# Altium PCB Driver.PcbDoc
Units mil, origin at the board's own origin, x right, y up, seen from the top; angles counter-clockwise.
Board outline 3750 x 2325 mil, 2 copper layers (Top Layer, Bottom Layer); 49 components, 30 nets, 142 pads, 61 vias.
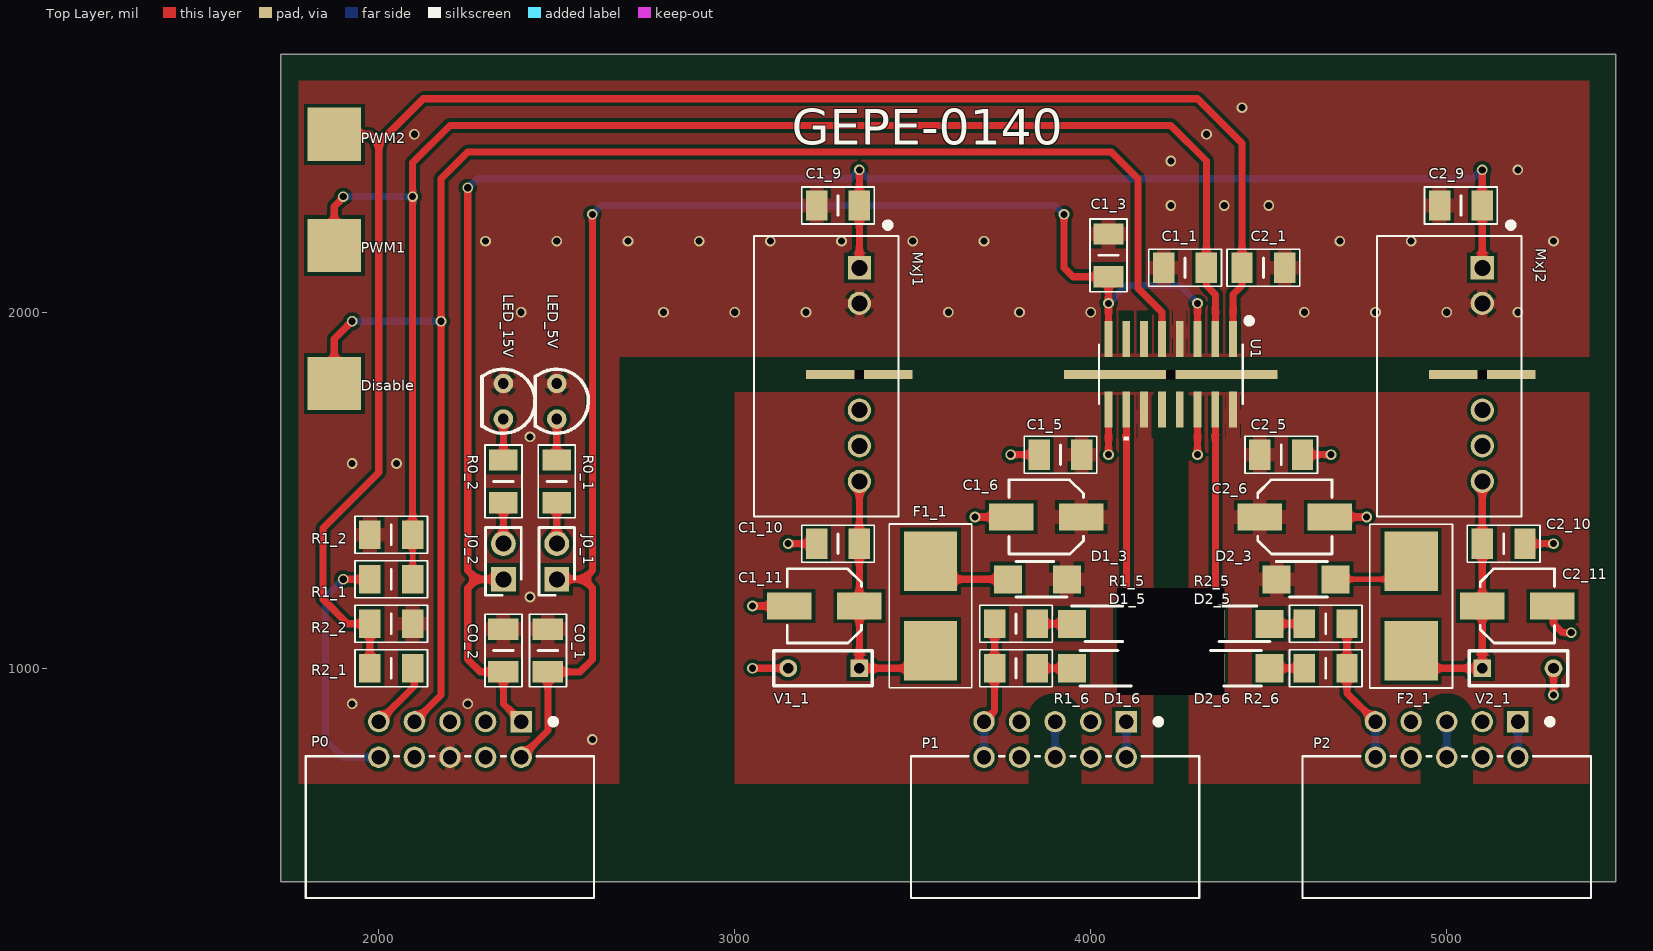
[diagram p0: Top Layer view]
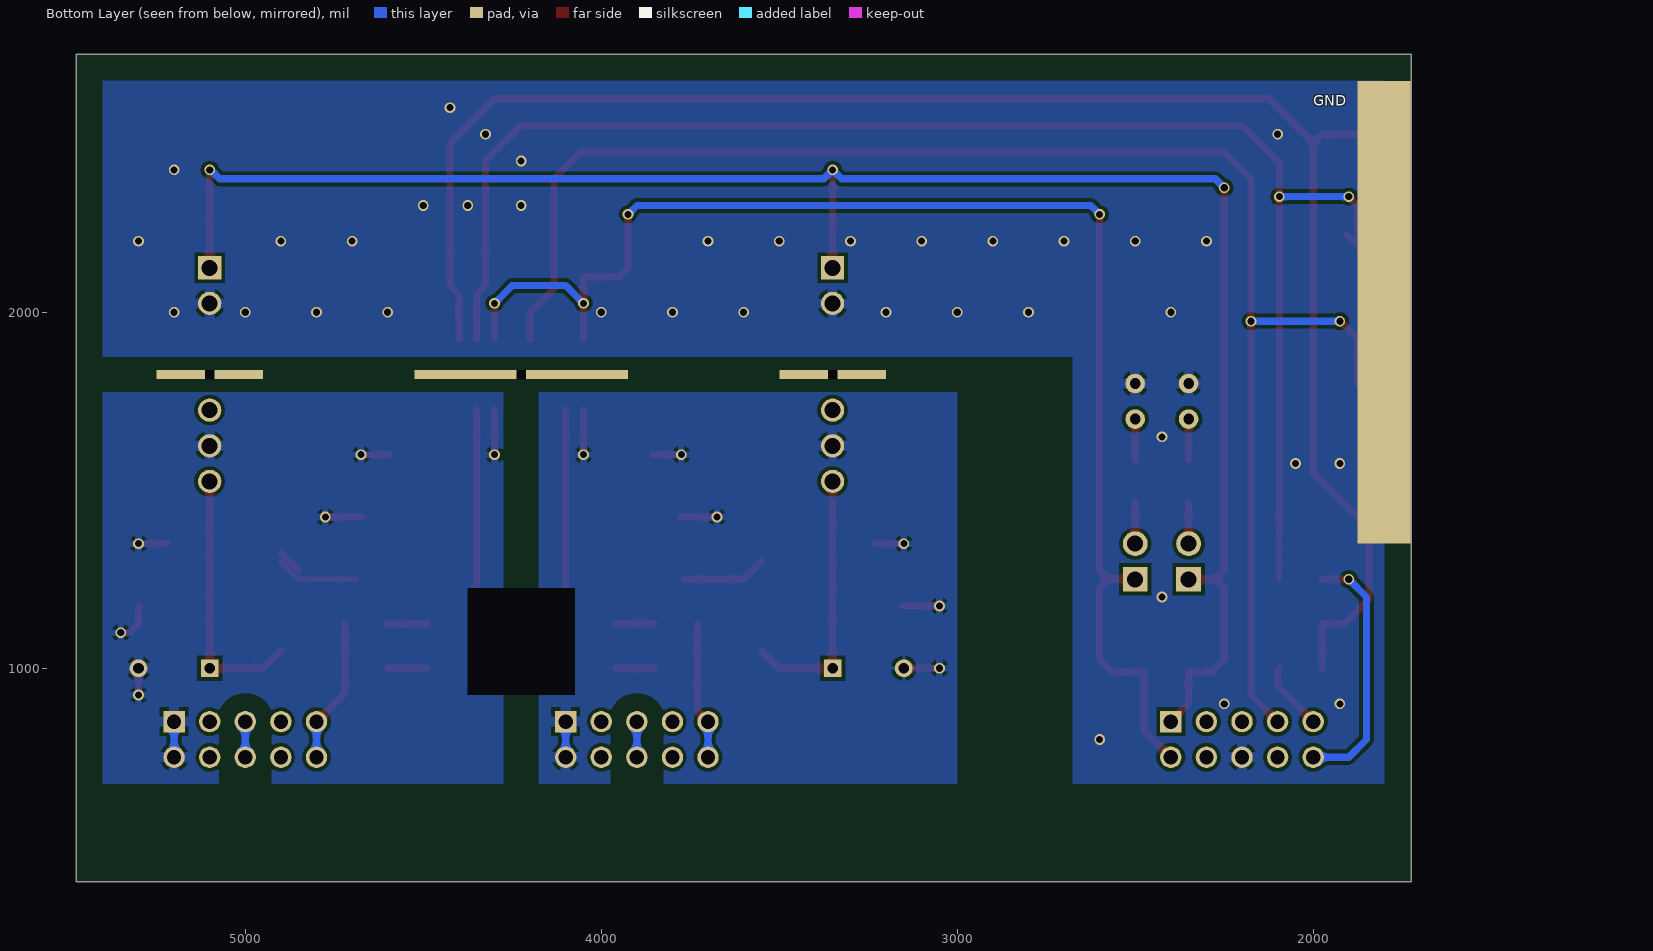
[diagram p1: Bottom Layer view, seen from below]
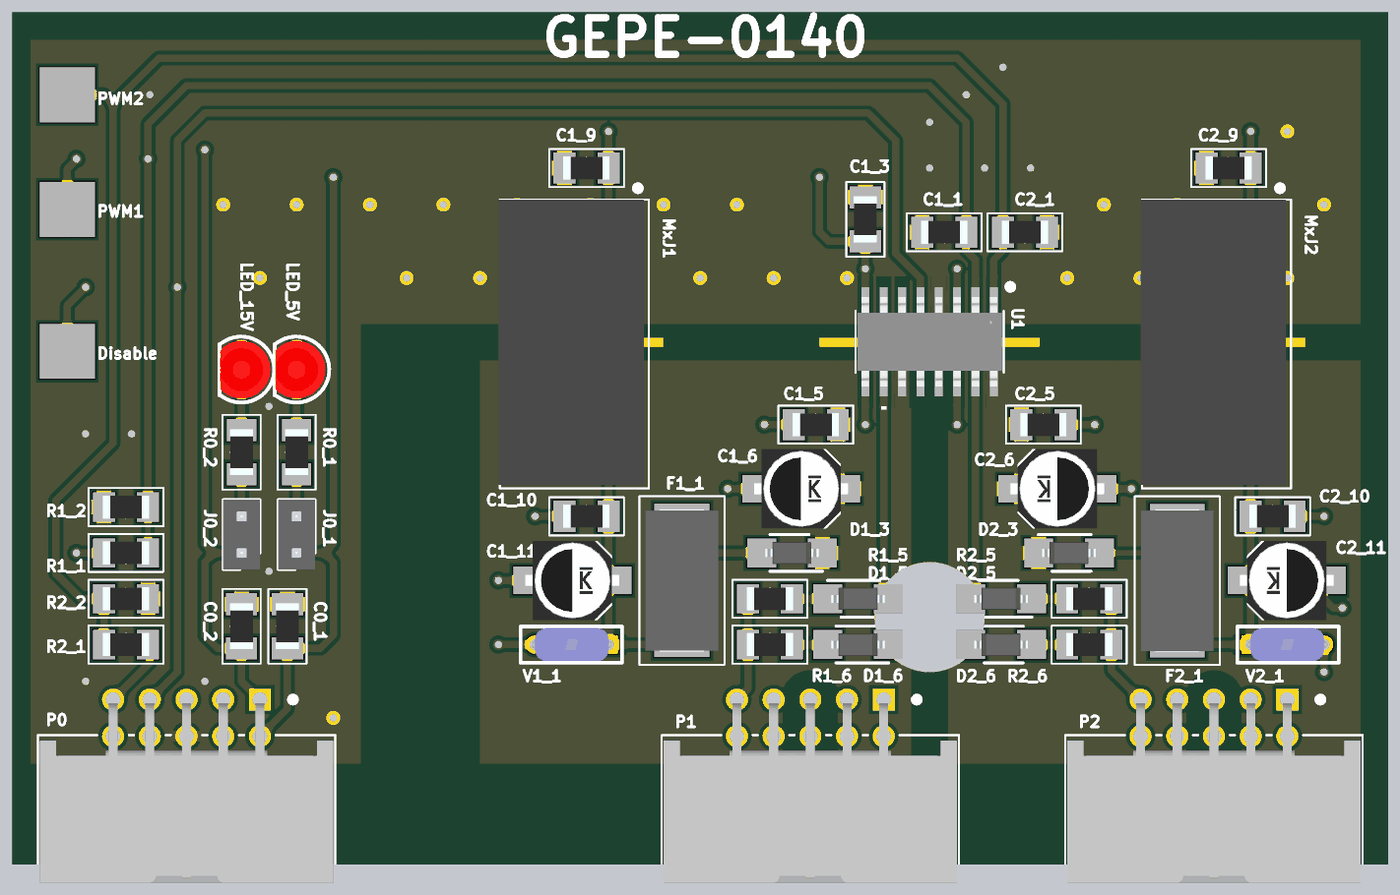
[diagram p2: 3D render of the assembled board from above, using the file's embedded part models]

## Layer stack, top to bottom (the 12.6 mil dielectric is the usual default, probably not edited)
Top Solder: solder mask 0.4, Solder Resist, Dk 3.5
Top Layer: signal copper 1.4
Dielectric 1: dielectric 12.6, FR-4, Dk 4.8
Bottom Layer: signal copper 1.4
Bottom Solder: solder mask 0.4, Solder Resist, Dk 3.5

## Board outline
1725,2725 5475,2725 5475,400 1725,400

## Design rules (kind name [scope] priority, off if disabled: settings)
Clearance Clearance_NetP2_5_GND [InNet('NetP2_5') vs InNet('GND_ISO2')] p1: gap=50 ignorepadtopadclearanceinfootprint=FALSE
Clearance Clearance_NetP2_Vcc [InNet('NetP2_5') vs InNet('NetC2_5_1')] p2: gap=50 ignorepadtopadclearanceinfootprint=FALSE
Clearance Clearance_NetP1_5_GND [InNet('NetP1_5') vs InNet('GND_ISO1')] p3: gap=50 ignorepadtopadclearanceinfootprint=FALSE
Clearance Clearance_NetP1_5_Vcc [InNet('NetP1_5') vs InNet('NetC1_5_1')] p4: gap=50 ignorepadtopadclearanceinfootprint=FALSE
Clearance "Stitching GND_ISO2" [IsStitchingVia and InNet('GND_ISO2') vs (IsVia and (Not IsStitchingVia)) Or IsPad] p5: gap=10 ignorepadtopadclearanceinfootprint=FALSE
Clearance [All] p6: gap=10 ignorepadtopadclearanceinfootprint=FALSE
ComponentClearance [All] p1: gap=-5 collisioncheckmode=3 verticalgap=10 showdistances=FALSE
DiffPairsRouting [All] p1: maxlimit=10 minlimit=10 mostfreqgap=10 substack1={C0840327-101B-4FFC-97E3-E8047B987EDC} toplayer_{c0840327-101b-4ffc-97e3-e8047b987edc}_minwidth=15 toplayer_{c0840327-101b-4ffc-97e3-e8047b987edc}_maxwidth=15 toplayer_{c0840327-101b-4ffc-97e3-e8047b987edc}_prefwidth=15 bottomlayer_{c0840327-101b-4ffc-97e3-e8047b987edc}_minwidth=15 bottomlayer_{c0840327-101b-4ffc-97e3-e8047b987edc}_maxwidth=15 bottomlayer_{c0840327-101b-4ffc-97e3-e8047b987edc}_prefwidth=15 toplayer_minwidth=15 toplayer_maxwidth=15 toplayer_prefwidth=15 bottomlayer_minwidth=15 bottomlayer_maxwidth=15 bottomlayer_prefwidth=15 substack2={2EBC8DE4-42E5-4D92-BB54-68FCB327EC1F} toplayer_{2ebc8de4-42e5-4d92-bb54-68fcb327ec1f}_minwidth=15 toplayer_{2ebc8de4-42e5-4d92-bb54-68fcb327ec1f}_maxwidth=15 toplayer_{2ebc8de4-42e5-4d92-bb54-68fcb327ec1f}_prefwidth=15 bottomlayer_{2ebc8de4-42e5-4d92-bb54-68fcb327ec1f}_minwidth=15 bottomlayer_{2ebc8de4-42e5-4d92-bb54-68fcb327ec1f}_maxwidth=15 bottomlayer_{2ebc8de4-42e5-4d92-bb54-68fcb327ec1f}_prefwidth=15 substack3={B410F142-04A1-4626-878C-5488EA430582} toplayer_{b410f142-04a1-4626-878c-5488ea430582}_minwidth=15 toplayer_{b410f142-04a1-4626-878c-5488ea430582}_maxwidth=15 toplayer_{b410f142-04a1-4626-878c-5488ea430582}_prefwidth=15 bottomlayer_{b410f142-04a1-4626-878c-5488ea430582}_minwidth=15 bottomlayer_{b410f142-04a1-4626-878c-5488ea430582}_maxwidth=15 bottomlayer_{b410f142-04a1-4626-878c-5488ea430582}_prefwidth=15 substack4={F83C5744-CF29-490E-B97B-F7943CBAD45F} toplayer_{f83c5744-cf29-490e-b97b-f7943cbad45f}_minwidth=15 toplayer_{f83c5744-cf29-490e-b97b-f7943cbad45f}_maxwidth=15 toplayer_{f83c5744-cf29-490e-b97b-f7943cbad45f}_prefwidth=15 bottomlayer_{f83c5744-cf29-490e-b97b-f7943cbad45f}_minwidth=15 bottomlayer_{f83c5744-cf29-490e-b97b-f7943cbad45f}_maxwidth=15 bottomlayer_{f83c5744-cf29-490e-b97b-f7943cbad45f}_prefwidth=15 substack5={FE27DC28-8263-47E9-9FA0-F4B9E94EB1D7} toplayer_{fe27dc28-8263-47e9-9fa0-f4b9e94eb1d7}_minwidth=15 toplayer_{fe27dc28-8263-47e9-9fa0-f4b9e94eb1d7}_maxwidth=15 toplayer_{fe27dc28-8263-47e9-9fa0-f4b9e94eb1d7}_prefwidth=15 bottomlayer_{fe27dc28-8263-47e9-9fa0-f4b9e94eb1d7}_minwidth=15 bottomlayer_{fe27dc28-8263-47e9-9fa0-f4b9e94eb1d7}_maxwidth=15 bottomlayer_{fe27dc28-8263-47e9-9fa0-f4b9e94eb1d7}_prefwidth=15 maxuncoupledlength=500
Height [All] p1: minheight=0 maxheight=10000 prefheight=500
HoleSize [All] p1: absolutevalues=TRUE maxlimit=1000 minlimit=1 maxpercent=80.000 minpercent=20.000
PolygonConnect [All] p1: connectstyle=Relief reliefconductorwidth=10 reliefentries=4 polygonreliefangle="90 Angle" airgapwidth=10
RoutingVias [All] p1: holewidth=20 width=30 viastyle="Through Hole" minholewidth=15 minwidth=25 maxholewidth=28 maxwidth=50
SilkToSilkClearance [All] p1: silktosilkclearance=0
SilkToSolderMaskClearance [IsPad] p1: minsilkscreentomaskgap=5 clearancetoexposedcopper=TRUE
SolderMaskExpansion [All] p1: expansion=4 istentingtop=FALSE
Width [All] p1: maxlimit=30 minlimit=15 preferedwidth=20 substack1={C0840327-101B-4FFC-97E3-E8047B987EDC} substack2={2EBC8DE4-42E5-4D92-BB54-68FCB327EC1F} substack3={B410F142-04A1-4626-878C-5488EA430582} substack4={F83C5744-CF29-490E-B97B-F7943CBAD45F} substack5={FE27DC28-8263-47E9-9FA0-F4B9E94EB1D7}
24 further rules are at their usual default settings.

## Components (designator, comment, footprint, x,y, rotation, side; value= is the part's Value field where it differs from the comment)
C0_1 "CAP" CAP1206_SMD 2475,1050 r90 top
C0_2 "CAP" CAP1206_SMD 2350,1050 r90 top
C1_1 "CAP" CAP1206_SMD 4265,2125 r180 top
C1_3 "CAP" CAP1206_SMD 4050,2160 r90 top
C1_5 "CAP" CAP1206_SMD 3915,1600 r180 top
C1_6 "CAP" CAP_ELETRO_SMD_6.3X7.7 3875,1425 r180 top
C1_9 "CAP" CAP1206_SMD 3290,2300 r180 top
C1_10 "CAP" CAP1206_SMD 3290,1350 r180 top
C1_11 "CAP" CAP_ELETRO_SMD_6.3X7.7 3251.57,1175 r180 top
C2_1 "CAP" CAP1206_SMD 4485,2125 r0 top
C2_5 "CAP" CAP1206_SMD 4535,1600 r0 top
C2_6 "CAP" CAP_ELETRO_SMD_6.3X7.7 4573.43,1425 r0 top
C2_9 "CAP" CAP1206_SMD 5040,2300 r180 top
C2_10 "CAP" CAP1206_SMD 5160,1350 r0 top
C2_11 "CAP" CAP_ELETRO_SMD_6.3X7.7 5198.43,1175 r0 top
D1_3 "TLHR5400-AS12Z" DIODE_SMD_SOD123 3850,1250 r180 top
D1_5 "TLHR5400-AS12Z" DIODE_SMD_SOD123 4030,1125 r0 top
D1_6 "TLHR5400-AS12Z" DIODE_SMD_SOD123 4030,1000 r180 top
D2_3 "TLHR5400-AS12Z" DIODE_SMD_SOD123 4605,1250 r0 top
D2_5 "TLHR5400-AS12Z" DIODE_SMD_SOD123 4420,1125 r180 top
D2_6 "TLHR5400-AS12Z" DIODE_SMD_SOD123 4420,1000 r0 top
Disable "TB004-508-02BE" TestPoint#1 1875,1800 r90 top
F1_1 "Fuse_0154" FUSE_0154 3550,1175 r90 top
F2_1 "Fuse_0154" FUSE_0154 4900,1174.41 r90 top
GND "TB004-508-02BE" TestPoint#2 1800,2000 r0 top
J0_1 "TB004-508-02BE" HEADER_MALE_TH_2P_2.54 2500,1250 r0 top
J0_2 "TB004-508-02BE" HEADER_MALE_TH_2P_2.54 2350,1250 r0 top
LED_5V "TLHR5400-AS12Z" "LED_TH_2.54 (SMALL)" 2500,1800 r270 top
LED_15V "TLHR5400-AS12Z" "LED_TH_2.54 (SMALL)" 2350,1800 r270 top
MxJ1 "MGJ2D152005SC" MGJ2_MUR 3350,2125 r270 top
MxJ2 "MGJ2D152005SC" MGJ2_MUR 5100,2125 r270 top
P0 "5103311-1" CONN_5103311-1_TYC 2400,750 r180 top
P1 "5103311-1" CONN_5103311-1_TYC 4100,750 r180 top
P2 "5103311-1" CONN_5103311-1_TYC 5200,750 r180 top
PWM1 "TB004-508-02BE" TESTPOINT 1875,2187.5 r270 top
PWM2 "TB004-508-02BE" TESTPOINT 1875,2500 r270 top
R0_1 "" RESIS_SMD_1206 2500,1525 r270 top
R0_2 "" RESIS_SMD_1206 2350,1525 r270 top
R1_1 "" RESIS_SMD_1206 2035,1250 r0 top
R1_2 "" RESIS_SMD_1206 2035,1375 r0 top
R1_5 "Res1" RESIS_SMD_1206 3790,1125 r180 top
R1_6 "Res1" RESIS_SMD_1206 3790,1000 r180 top
R2_1 "" RESIS_SMD_1206 2035,1000 r180 top
R2_2 "" RESIS_SMD_1206 2035,1125 r180 top
R2_5 "Res1" RESIS_SMD_1206 4660,1125 r0 top
R2_6 "Res1" RESIS_SMD_1206 4660,1000 r0 top
U1 "ADUM3223ARZ" ADUM3223 4225,1826 r270 top
V1_1 "B72220S131K101" "CAP_TH _5.08" 3250,1000 r180 top
V2_1 "B72220S131K101" "CAP_TH _5.08" 5200,1000 r0 top

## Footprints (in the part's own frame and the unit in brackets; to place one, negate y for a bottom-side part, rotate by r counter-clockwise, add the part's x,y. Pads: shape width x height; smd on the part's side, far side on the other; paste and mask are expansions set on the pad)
ADUM3223 [mil]
  rect 100x22 smd paste+0 mask+0: 1(-99,175) 2(-99,125) 3(-99,75) 4(-99,25) 5(-99,-25) 6(-99,-75) 7(-99,-125) 8(-99,-175) 9(99,-175) 10(99,-125) 11(99,-75) 12(99,-25) 13(99,25) 14(99,75) 15(99,125) 16(99,175)
  silkscreen extent -151,-202 185,221, body extent -122,-197 122,197, height 69
CAP1206_SMD [mil]
  rect 60x85 smd: 1(-60,0) 2(60,0)
  silkscreen extent -102,-52 102,52, body extent -63,-31 63,31, height 26
CAP_ELETRO_SMD_6.3X7.7 [mm]
  rect 3.175x1.905 smd: 1(-2.5,0) 2(2.5,0)
  silkscreen extent -2.65,-2.65 2.65,2.65, body extent -3.25,-2.75 3.25,2.75, height 5.74
"CAP_TH _5.08" [mil]
  rect 50x50 hole 30: 1(-100,0)
  round 50 hole 30: 2(100,0)
  silkscreen extent -137,-49 140,49, body extent -110,-45 110,45, height 250
CONN_5103311-1_TYC [mil]
  rect 60x60 hole 40 mask+0: 1(0,-100)
  round 60 hole 40 mask+0: 2(0,0) 3(100,-100) 4(100,0) 5(200,-100) 6(200,0) 7(300,-100) 8(300,0) 9(400,-100) 10(400,0)
  silkscreen extent -205,-101 605,395, body extent -200,-90 600,400, height 370
DIODE_SMD_SOD123 [mm]
  rect 2x2 smd: 1(-2.1,0) 2(2.1,0)
  silkscreen extent -2.13,-1.27 1.52,1.27, body extent -1.85,-0.77 1.85,0.78, height 1.45
FUSE_0154 [mil]
  rect 167x150 smd: 1(-125.59,0) 2(125.59,0)
  silkscreen extent -230,-116 230,116, body extent -194,-99 194,99, height 154
HEADER_MALE_TH_2P_2.54 [mil]
  rect 70x70 hole 45: 1(0,0)
  round 70 hole 45: 2(0,100)
  silkscreen extent -50,-45 50,145, body extent -50,-45 50,145, height 338
"LED_TH_2.54 (SMALL)" [mil]
  round 55 hole 30: 1(0,0) 2(100,0)
  silkscreen extent -40,-60 140,89, body extent -28,-59 129,79, height 212
MGJ2_MUR [mil]
  rect 65x65 hole 45 mask+0: 1(0,0)
  round 65 hole 45 mask+0: 2(100,0) 5(400,0) 6(500,0) 7(600,0)
  silkscreen extent -121,-296 699,110, body extent -89,-300 689,96, height 502
RESIS_SMD_1206 [mil]
  rect 60x80 smd: 1(-60,0) 2(60,0)
  silkscreen extent -102,-52 102,52, body extent -63,-31 63,31, height 30
TestPoint#1 [mil]
  rect 150x150 smd: 1(0,0)
TestPoint#2 [mil]
  rect 150x1300 smd far side: 1(0,0)
TESTPOINT [mil]
  rect 150x150 smd: 1(0,0)

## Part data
C0_1 C0_2 C1_1 C1_3 C1_5 C1_6 C1_9 C1_10 C1_11 C2_1 C2_5 C2_6 C2_9 C2_10 C2_11: "Capacitor", Manufacturer_Name=Kemet, Manufacturer_Part_Number=C1206X475K3RACAUTO7210, Mouser Part Number=80-C1206X475K3RAUTLR
D1_3 D1_5 D1_6 D2_3 D2_5 D2_6: library part Diode, "Diode", Manufacturer_Name=Vishay
Disable GND PWM1 PWM2: library part TestPoint, "Connector", Manufacturer_Name="CUI Devices", Mouser Part Number=490-TB004-508-02BE
F1_1 F2_1: "Fuse", Manufacturer_Name=LITTELFUSE, Manufacturer_Part_Number=0154002.DRL, Mouser2 Part Number=576-0154002.DRL
J0_1 J0_2: library part Con_Header_2P, "Connector", Manufacturer_Name="CUI Devices", Mouser Part Number=490-TB004-508-02BE
LED_5V LED_15V: library part LED, "LED", Manufacturer_Name=Vishay
MxJ1 MxJ2: "No Description Available", Mfr_Name=Murata
P0 P1 P2: library part Con_Header_5103311-1, "No Description Available", Mfr_Name="TE Connectivity"
R0_1 R0_2 R1_1 R1_2 R1_5 R1_6 R2_1 R2_2 R2_5 R2_6: library part Resistor, "Resistor"
U1: "No Description Available"
V1_1 V2_1: library part Varistor, "No Description Available", Mfr_Name=TDK

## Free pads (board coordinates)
  rect 300x25 hole 25 square mask+0: 1(3350,1825) 1(5100,1825)
  rect 25x300 hole 300 square mask+0: 1(4225,1075)
  rect 600x25 hole 25 square mask+0: 1(4225,1825)

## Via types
v1: diameter 30, hole 20, Top Layer to Bottom Layer, tented top, 37 vias
v2: diameter 30, hole 20, Top Layer to Bottom Layer, 24 vias

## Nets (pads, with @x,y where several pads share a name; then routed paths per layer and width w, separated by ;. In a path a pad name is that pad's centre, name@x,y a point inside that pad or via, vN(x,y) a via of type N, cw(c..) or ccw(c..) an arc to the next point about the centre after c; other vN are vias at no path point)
GND: C0_1.2 C0_2.2 C1_1.2 C1_3.2 C1_9.2 C2_1.2 C2_9.2 GND.1 LED_5V.1 LED_15V.1 MxJ1.2 MxJ2.2 P0.6 R1_2.1 R2_2.1 U1.4
  other v1: 1925,900 2250,900 2425,1200 1925,1575 2050,1575 2425,1650 4225,2300 4375,2300 4500,2300 4225,2425 2100,2500 4325,2500 4425,2575
  other v2: 2600,800 2400,2000 2800,2000 3000,2000 3200,2000 3600,2000 3800,2000 4000,2000 4600,2000 4800,2000 5000,2000 5200,2000 2300,2200 2500,2200 2700,2200 2900,2200 3100,2200 3300,2200 3500,2200 3700,2200 4700,2200 4900,2200 5300,2200 5200,2400
GND_ISO1: C1_5.2 C1_6.2 C1_10.2 C1_11.2 MxJ1.6 P1.1 P1.2 U1.9 V1_1.2 | length 691.7
  Top Layer w20: v1(3050,1000) V1_1.2 ; v1(3050,1175) C1_11.2 ; v1(3150,1350) C1_10.2 ; v1(3675,1425) C1_6.2 ; v1(3775,1600) C1_5.2 ; v1(4050,1600) U1.9
  Bottom Layer w20: P1.2 P1.1
GND_ISO2: C2_5.2 C2_6.2 C2_10.2 C2_11.2 MxJ2.6 P2.1 P2.2 U1.14 V2_1.2 | length 676.8
  Top Layer w20: v1(4300,1600) U1.14 ; C2_5.2 v1(4675,1600) ; C2_6.2 v1(4775,1425) ; C2_10.2 v1(5300,1350) ; C2_11.2 5300,1171.85 5300,1125 5325,1100 v1(5350,1100) ; v1(5300,925) V2_1.2
  Bottom Layer w20: P2.2 P2.1
NetC0_1_1: C0_1.1 C1_3.1 J0_1.1 P0.2 U1.3 U1.8 | length 3953.8
  Top Layer w20: P0.2 2475,825 C0_1.1 2565,990 2600,1025 2600,1225 2575,1250 ; J0_1.1 2575,1250 ; v1(2600,2275) 2600,1275 2575,1250 ; v1(3925,2275) 3925,2125 3950,2100 C1_3.1 v1(4050,2025) U1.8 ; U1.3 v1(4300,2025)
  Bottom Layer w20: v1(2600,2275) 2625,2300 3900,2300 v1(3925,2275) ; v1(4050,2025) 4100,2075 4250,2075 v1(4300,2025)
NetC0_2_1: C0_2.1 C1_9.1 C2_9.1 J0_2.1 MxJ1.1 MxJ2.1 P0.1 | length 5137.3
  Top Layer w20: v1(2250,2350) 2250,1275 2275,1250 ; J0_2.1 2275,1250 ; P0.1 2350,900 C0_2.1 2285,990 2250,1025 2250,1225 2275,1250 ; MxJ1.1 C1_9.1 v1(3350,2400) ; MxJ2.1 C2_9.1 v1(5100,2400)
  Bottom Layer w20: v1(2250,2350) 2275,2375 3325,2375 v1(3350,2400) 3375,2375 5072.29,2375 5097.29,2400 v1(5100,2400)
NetC1_1_1: C1_1.1 PWM1.1 R1_1.2 R1_2.2 U1.2 | length 4381.7
  Top Layer w15: R1_1.2 R1_2.2
  Top Layer w20: v1(1900,2325) 1900,2322.29 1875,2297.29 PWM1.1 PWM1.1@1905.78,2218.28 ; R1_2.2 v1(2095,2325) 2095,2420 2200,2525 4225,2525 4325,2425 C1_1.1 4325,2075 4350,2050 U1.2
  Bottom Layer w20: v1(1900,2325) v1(2095,2325)
NetC1_5_1: C1_5.1 C1_6.1 D1_3.1 U1.11
NetC1_10_1: C1_10.1 C1_11.1 F1_1.1 MxJ1.7 V1_1.1 | length 745.5
  Top Layer w20: MxJ1.7 C1_10.1 C1_11.1 V1_1.1 3500.59,1000 F1_1.1
NetC2_1_1: C2_1.1 PWM2.1 R2_1.2 R2_2.2 U1.1 | length 4855
  Top Layer w20: PWM2.1 1975,2500 2000,2475 ; R2_1.2 R2_2.2 1912.5,1125 1843.75,1193.75 1843.75,1393.75 2000,1550 2000,2475 ; U1.1 4400,2050 4425,2075 C2_1.1 4425,2475 4300,2600 2125,2600 2000,2475
NetC2_5_1: C2_5.1 C2_6.1 D2_3.1 U1.16
NetC2_10_1: C2_10.1 C2_11.1 F2_1.1 MxJ2.7 V2_1.1 | length 745.7
  Top Layer w20: F2_1.1@4900,1050 4950,1000 V2_1.1 C2_11.1 C2_10.1 MxJ2.7
NetD1_3_2: D1_3.2 F1_1.2 | length 238.3
  Top Layer w20: F1_1.2 3600.59,1250 D1_3.2
NetD1_5_1: D1_5.1 R1_5.1 | length 110
  Top Layer w20: R1_5.1 D1_5.1@3960,1125
NetD1_5_2: D1_5.2 D1_6.1 U1.10 | length 727
  Top Layer w20: D1_6.1@4100,1000 4100,1125 U1.10
NetD1_6_2: D1_6.2 R1_6.1 | length 110
  Top Layer w20: R1_6.1 D1_6.2@3960,1000
NetD2_3_2: D2_3.2 F2_1.2 | length 305.4
  Top Layer w15: D2_3.2 4850,1250 F2_1.2
  Top Layer w20: F2_1.2@4848.82,1274.41 F2_1.2@4900,1325.59
NetD2_5_1: D2_5.1 R2_5.1 | length 110
  Top Layer w20: D2_5.1@4490,1125 R2_5.1
NetD2_5_2: D2_5.2 D2_6.1 U1.15 | length 727
  Top Layer w20: D2_6.1@4350,1000 4350,1125 U1.15
NetD2_6_2: D2_6.2 R2_6.1 | length 110
  Top Layer w20: D2_6.2@4490,1000 R2_6.1
NetDisable_1: Disable.1 P0.7 U1.5 | length 4499.4
  Top Layer w20: Disable.1 1875,1925 v1(1925,1975) ; P0.7 2175,925 v1(2175,1975) 2175,2375 2250,2450 4057.5,2450 4132.5,2375 4132.5,2067.5 4200,2000 U1.5
  Bottom Layer w20: v1(1925,1975) v1(2175,1975)
NetJ0_1_2: J0_1.2 R0_1.2 | length 115
  Top Layer w20: J0_1.2 R0_1.2
NetJ0_2_2: J0_2.2 R0_2.2 | length 115
  Top Layer w20: J0_2.2 R0_2.2
NetLED_5V_2: LED_5V.2 R0_1.1 | length 115
  Top Layer w20: R0_1.1 LED_5V.2
NetLED_15V_2: LED_15V.2 R0_2.1 | length 115
  Top Layer w20: R0_2.1 LED_15V.2
NetP0_9: P0.9 R2_1.1 | length 193.5
  Top Layer w20: P0.9 2100,950 2100,995 R2_1.1
NetP0_10: P0.10 R1_1.1 | length 716.4
  Top Layer w20: v1(1900,1250) R1_1.1
  Bottom Layer w20: v1(1900,1250) 1850,1200 1850,800 1900,750 P0.10
NetP1_5: P1.5 P1.6 | length 100
  Bottom Layer w20: P1.6 P1.5
NetP1_9: P1.9 P1.10 R1_5.2 R1_6.2 | length 387.4
  Top Layer w20: P1.9 3730,880 R1_6.2 R1_5.2
  Bottom Layer w20: P1.10 P1.9
NetP2_5: P2.5 P2.6 | length 100
  Bottom Layer w20: P2.6 P2.5
NetP2_9: P2.9 P2.10 R2_5.2 R2_6.2 | length 408.1
  Top Layer w20: R2_5.2 R2_6.2 4720,930 P2.9
  Bottom Layer w20: P2.10 P2.9
pads on no net: MxJ1.5 MxJ2.5 P0.3 P0.4 P0.5 P0.8 P1.3 P1.4 P1.7 P1.8 P2.3 P2.4 P2.7 P2.8 U1.6 U1.7 U1.12 U1.13

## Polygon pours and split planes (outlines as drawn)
NetC1_5_1 on Top Layer "NONET_L01_P-001" (solid, remove dead copper, pour order 142): 3000,675 3825,675 3825,850 3975,850 3975,675 4175,675 4175,1775 3000,1775
NetC2_5_1 on Top Layer "NETC2_5_1_L01_P140" (solid, remove dead copper, pour order 140): 4275,1775 4275,675 4925,675 4925,850 5075,850 5075,675 5400,675 5400,1775
GND on Top Layer "GND_L01_P126" (solid, remove dead copper, pour order 126): 2675,675 1775,675 1775,2650 5400,2650 5400,1875 2675,1875
GND_ISO1 on Bottom Layer "GND_ISO1_L02_P130" (solid, remove dead copper, pour order 130): 4175,675 4175,1775 3000,1775 3000,675 3825,675 3825,850 3975,850 3975,675
GND_ISO2 on Bottom Layer "GND_ISO2_L02_P138" (solid, remove dead copper, pour order 138): 4275,675 4925,675 4925,850 5075,850 5075,675 5400,675 5400,1775 4275,1775
GND on Bottom Layer "GND_L02_P134" (solid, remove dead copper, pour order 134): 2675,675 1800,675 1800,2650 5400,2650 5400,1875 2675,1875

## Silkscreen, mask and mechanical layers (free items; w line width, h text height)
Top Overlay:
  text "GEPE-0140" at 3160,2470 h100
Board Outline:
  lines w10: 6000,-23 6001.07,-21.93 ; 1725,400 5475,400 5475,2179.48 5475,2202 5475,2724.97 1747.26,2724.97 1727.03,2724.97 1725,2722.94 1725,2702.71 1725,400

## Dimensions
4250,355 to 6550,3500 on Mechanical 7
2400,400 to 4305,400 on Mechanical 7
